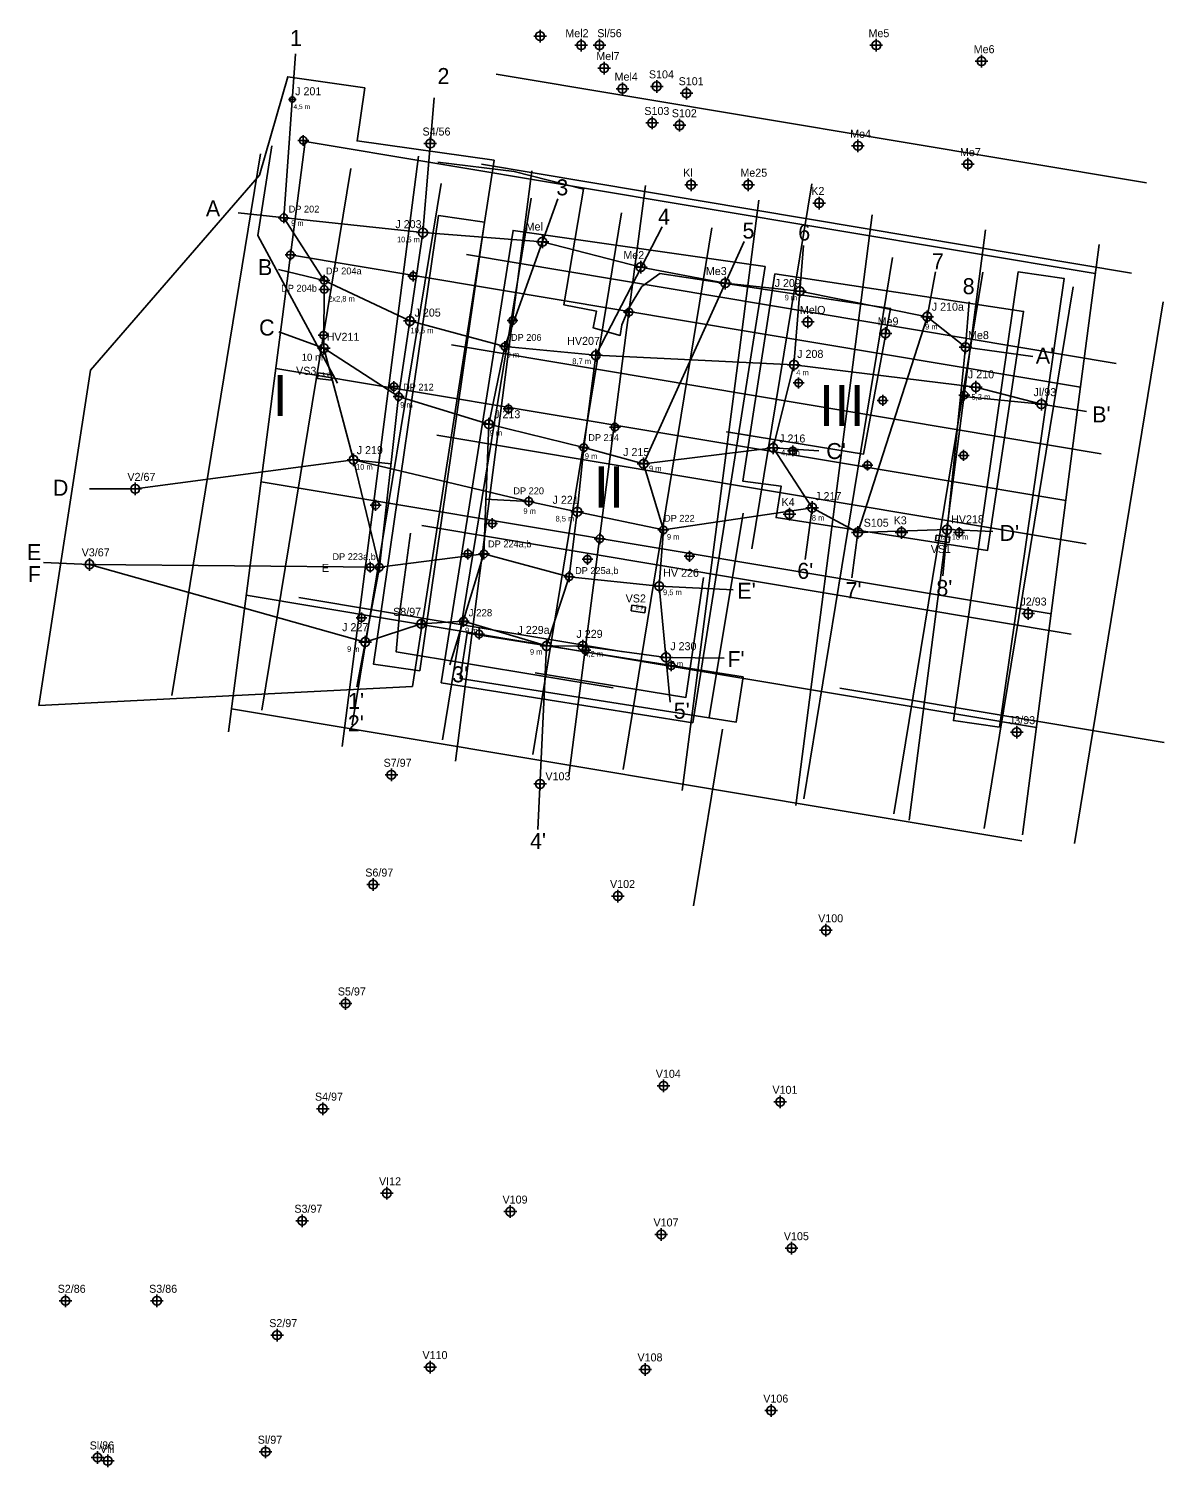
# Model space of a CAD drawing. Extents: x -597749 to -595427, y -1168718 to -1166900.
# Drawn here: x -597567 to -597070, y -1168718 to -1168089 of the extents above; entities that cross this region are included whole.
import ezdxf

# ---------------------------------------------------------------- set-up
doc = ezdxf.new("R2010")
doc.units = 0
for name, color, linetype in [('13_archivní průzkum', 7, 'Continuous'), ('40 m vrty', 7, 'Continuous'), ('50 m', 7, 'Continuous'), ('50 m vrty', 7, 'Continuous'), ('groma_bod', 7, 'Continuous'), ('groma_cislo', 7, 'Continuous'), ('IG řezy', 7, 'Continuous'), ('Nova Šrafy Hranice', 7, 'Continuous'), ('oblasti', 7, 'Continuous'), ('pomocna', 7, 'Continuous'), ('Silový kabel', 7, 'Continuous'), ('vsakovací jímky', 7, 'Continuous'), ('zaměření 24_4_2017', 7, 'Continuous')]:
    doc.layers.add(name, color=color, linetype=linetype)

# ---------------------------------------------------------------- blocks, each defined once
blk = doc.blocks.new('IG vrt OK')
for p, q in [((0, 0.198), (0, -0.198)), ((-0.198, 0), (0.198, 0))]:
    blk.add_line(p, q)
blk.add_circle((0, 0), 0.138)

msp = doc.modelspace()

# ---------------------------------------------------------------- linework, layer by layer
for p, q in [((-597362.16, -1168108.59), (-597077.9, -1168156.23)), ((-597465.24, -1168143.45), (-597504.06, -1168380.28)), ((-597425.77, -1168149.92), (-597464.59, -1168386.75)), ((-597368.66, -1168148.05), (-597084.48, -1168195.68)), ((-597386.29, -1168156.4), (-597425.12, -1168393.22)), ((-597224.18, -1168156.54), (-597250.35, -1168316.14)), ((-597346.82, -1168162.87), (-597385.65, -1168399.69)), ((-597307.35, -1168169.34), (-597346.17, -1168406.17)), ((-597267.87, -1168175.81), (-597306.7, -1168412.64)), ((-597375.16, -1168187.52), (-597091.07, -1168235.14)), ((-597188.93, -1168188.75), (-597227.75, -1168425.58)), ((-597149.46, -1168195.22), (-597188.28, -1168432.05)), ((-597109.98, -1168201.69), (-597148.81, -1168438.52)), ((-597070.51, -1168208.17), (-597109.33, -1168444.99)), ((-597381.66, -1168226.99), (-597097.65, -1168274.59)), ((-597388.16, -1168266.46), (-597104.24, -1168314.05)), ((-597394.66, -1168305.93), (-597110.82, -1168353.5)), ((-597448.45, -1168337.47), (-597306.58, -1168361.25)), ((-597211.99, -1168377.1), (-597070.11, -1168400.88)), ((-597263.29, -1168395.08), (-597275.95, -1168472.31))]:
    msp.add_line(p, q)
at = {"layer": '50 m'}
for p, q in [((-597445.71, -1168138.05), (-597100.27, -1168195.84)), ((-597452.14, -1168187.67), (-597106.7, -1168245.46)), ((-597458.57, -1168237.29), (-597113.13, -1168295.08)), ((-597465, -1168286.91), (-597119.56, -1168344.69)), ((-597471.43, -1168336.52), (-597125.99, -1168394.31)), ((-597477.86, -1168386.14), (-597132.42, -1168443.93))]:
    msp.add_line(p, q, dxfattribs=at)
for points in [[(-597445.72, -1168138.09), (-597454.2, -1168203.57), (-597479.17, -1168396.23)], [(-597396.13, -1168144.52), (-597404.61, -1168209.99), (-597429.58, -1168402.65)], [(-597346.54, -1168150.94), (-597355.03, -1168216.42), (-597380, -1168409.08)], [(-597296.96, -1168157.37), (-597305.44, -1168222.84), (-597330.41, -1168415.51)], [(-597247.37, -1168163.79), (-597255.86, -1168229.27), (-597280.83, -1168421.93)], [(-597197.79, -1168170.22), (-597206.27, -1168235.7), (-597231.24, -1168428.36)], [(-597148.2, -1168176.65), (-597156.69, -1168242.12), (-597181.65, -1168434.78)], [(-597098.62, -1168183.07), (-597107.1, -1168248.55), (-597132.07, -1168441.21)]]:
    msp.add_lwpolyline(points, dxfattribs=at)
at = {"layer": 'groma_bod'}
for p, q in [((-597438.23, -1168241.13), (-597438.23, -1168241.13)), ((-597438.12, -1168240.33), (-597438.12, -1168240.33)), ((-597436.25, -1168241.41), (-597436.25, -1168241.41)), ((-597436.14, -1168240.62), (-597436.14, -1168240.62)), ((-597168.02, -1168312.03), (-597168.02, -1168312.03)), ((-597167.9, -1168311.24), (-597167.9, -1168311.24)), ((-597166.04, -1168312.32), (-597166.04, -1168312.32)), ((-597165.92, -1168311.53), (-597165.92, -1168311.53)), ((-597300.95, -1168341.98), (-597300.95, -1168341.98)), ((-597298.97, -1168342.27), (-597298.97, -1168342.27)), ((-597301.07, -1168342.77), (-597301.07, -1168342.77)), ((-597299.09, -1168343.06), (-597299.09, -1168343.06))]:
    msp.add_line(p, q, dxfattribs=at)
at = {"layer": 'IG řezy'}
for points in [[(-597449.87, -1168099.8), (-597455.09, -1168171.45), (-597437.35, -1168198.8), (-597437.51, -1168228.48), (-597424.58, -1168277.25), (-597413.22, -1168324.22), (-597423.17, -1168376.6)], [(-597413.22, -1168324.22), (-597404.85, -1168249.6), (-597399.91, -1168216.57), (-597394.21, -1168177.95), (-597389.36, -1168119.07)], [(-597335.28, -1168163.16), (-597358.34, -1168227.78), (-597365.44, -1168261.65), (-597367.53, -1168318.28), (-597382.39, -1168366.95)], [(-597474.97, -1168169.32), (-597394.21, -1168177.95), (-597342, -1168182), (-597299, -1168193), (-597262, -1168200), (-597229.45, -1168203.52), (-597173.72, -1168214.7), (-597157, -1168228), (-597127.53, -1168232.16)], [(-597289.61, -1168175.34), (-597318.62, -1168231.59), (-597323.89, -1168271.9), (-597326.71, -1168299.99), (-597330.28, -1168328.41), (-597340.19, -1168358.66), (-597343.95, -1168438.98)], [(-597253.76, -1168181.78), (-597297.73, -1168279.03), (-597289.09, -1168307.9), (-597290.88, -1168332.38), (-597286.05, -1168383.2)], [(-597227.87, -1168183.59), (-597229.45, -1168203.52), (-597231.99, -1168235.71), (-597241.06, -1168272.03), (-597224.01, -1168298.2), (-597227.12, -1168320.8)], [(-597457.34, -1168194.1), (-597437.35, -1168198.8), (-597399.91, -1168216.57), (-597358.34, -1168227.78), (-597318.62, -1168231.59), (-597231.99, -1168235.71), (-597152.46, -1168245.5), (-597123.82, -1168252.94), (-597104.07, -1168256.09)], [(-597170.13, -1168195.02), (-597173.72, -1168214.86), (-597204, -1168309), (-597206.73, -1168328.81)], [(-597155.4, -1168208.24), (-597157, -1168228), (-597165.06, -1168307.79), (-597166.92, -1168328.03)], [(-597457.24, -1168221.35), (-597437.51, -1168228.48), (-597404.85, -1168249.6), (-597365.44, -1168261.65), (-597323.89, -1168271.9), (-597297.73, -1168279.03), (-597241.06, -1168272.03), (-597221.1, -1168273.32)], [(-597540, -1168290), (-597520, -1168290), (-597424.58, -1168277.25), (-597347.94, -1168295.43), (-597326.71, -1168299.99), (-597289.09, -1168307.9), (-597224.01, -1168298.2), (-597204, -1168309), (-597165.06, -1168307.79), (-597145.01, -1168308.67)], [(-597560.08, -1168322.21), (-597540, -1168323), (-597419.44, -1168356.96), (-597395, -1168349), (-597376.45, -1168347.85), (-597340.19, -1168358.66), (-597324.35, -1168358.7), (-597287.91, -1168363.64), (-597262.45, -1168363.98)], [(-597540, -1168323), (-597413.22, -1168324.22), (-597367.53, -1168318.42), (-597330.28, -1168328.41), (-597291.04, -1168332.46), (-597258.62, -1168334.11)]]:
    msp.add_lwpolyline(points, dxfattribs=at)
at = {"layer": 'Nova Šrafy Hranice'}
for p, q in [((-597254.18, -1168300.64), (-597269.01, -1168389.9)), ((-597269.01, -1168389.9), (-597269.04, -1168390.08))]:
    msp.add_line(p, q, dxfattribs=at)
at = {"layer": 'oblasti'}
for points in [[(-597363, -1168146.29), (-597398.78, -1168376.37), (-597562.09, -1168384.66), (-597539.58, -1168238.06), (-597465.72, -1168152.82), (-597453.34, -1168109.77), (-597419.62, -1168114.64), (-597422.97, -1168137.87)], [(-597244.57, -1168192.7), (-597276.27, -1168392.21), (-597386.22, -1168374.74), (-597354.79, -1168176.94)], [(-597240.32, -1168196), (-597131.62, -1168212.37), (-597147.37, -1168316.9), (-597239.79, -1168302.53), (-597237.65, -1168288.77), (-597254.4, -1168286.54)]]:
    msp.add_lwpolyline(points, close=True, dxfattribs=at)
at = {"layer": 'pomocna'}
for p, q in [((-597158.69, -1168244.88), (-597152.46, -1168245.5)), ((-597159.14, -1168249.41), (-597123.82, -1168252.94)), ((-597408.16, -1168279.09), (-597424.58, -1168277.25)), ((-597367.03, -1168294.51), (-597347.94, -1168295.43))]:
    msp.add_line(p, q, dxfattribs=at)
at = {"layer": 'Silový kabel'}
for points in [[(-597460.25, -1168140.03), (-597466.36, -1168179.17), (-597431.54, -1168243.72)], [(-597251.4, -1168266.68), (-597261.43, -1168265.05), (-597201.57, -1168274.75), (-597189.73, -1168211.07), (-597290.61, -1168195.88), (-597298.51, -1168201.51), (-597304.04, -1168210.66), (-597307.21, -1168218.22), (-597307.92, -1168222.88), (-597319.79, -1168219.55), (-597318.36, -1168212.28), (-597332.57, -1168209.53), (-597323.96, -1168158.92), (-597354.29, -1168151.22), (-597387.68, -1168147.18)], [(-597399.62, -1168309.28), (-597404.5, -1168344.65), (-597405.97, -1168361.2), (-597311.02, -1168376.98)], [(-597271.53, -1168328.77), (-597279.2, -1168381.17), (-597345.13, -1168370.36)]]:
    msp.add_lwpolyline(points, dxfattribs=at)
for points in [[(-597395.64, -1168369.58), (-597367.31, -1168173.42), (-597387.47, -1168170.51), (-597415.8, -1168366.67)], [(-597142.16, -1168394.22), (-597113.83, -1168198.06), (-597133.99, -1168195.15), (-597162.31, -1168391.31)], [(-597254.19, -1168372.16), (-597374.81, -1168353.06), (-597377.95, -1168372.89), (-597257.33, -1168391.99)]]:
    msp.add_lwpolyline(points, close=True, dxfattribs=at)
at = {"layer": 'vsakovací jímky'}
for points in [[(-597439.99, -1168239.25), (-597440.32, -1168241.65), (-597434.38, -1168242.49), (-597434.05, -1168240.12)], [(-597169.76, -1168310.16), (-597170.12, -1168312.53), (-597164.18, -1168313.4), (-597163.82, -1168311.03)], [(-597302.81, -1168340.9), (-597303.17, -1168343.27), (-597297.23, -1168344.14), (-597296.87, -1168341.77)]]:
    msp.add_lwpolyline(points, close=True, dxfattribs=at)

# ---------------------------------------------------------------- block references
at = {"layer": '13_archivní průzkum', "xscale": 13.9855072, "yscale": 13.9855072}
for p in [(-597343, -1168092), (-597325, -1168096), (-597317, -1168096), (-597196, -1168096), (-597315, -1168106), (-597150, -1168103), (-597307, -1168115), (-597292, -1168114), (-597279, -1168117), (-597294, -1168130), (-597282, -1168131), (-597391, -1168139), (-597204, -1168140), (-597156, -1168148), (-597277, -1168157), (-597252, -1168157), (-597221, -1168165), (-597342, -1168182), (-597299, -1168193), (-597262, -1168200), (-597226, -1168217), (-597192, -1168222), (-597157, -1168228), (-597123.82, -1168252.94), (-597520, -1168290), (-597234, -1168301), (-597204, -1168309), (-597185, -1168309), (-597540, -1168323), (-597129.57, -1168344.52), (-597395, -1168349), (-597134.6, -1168396.37), (-597408, -1168415), (-597343, -1168419), (-597416, -1168463), (-597309, -1168468), (-597218, -1168483), (-597428, -1168515), (-597289, -1168551), (-597238, -1168558), (-597438, -1168561), (-597410, -1168598), (-597356, -1168606), (-597447, -1168610), (-597290, -1168616), (-597233, -1168622), (-597550.5, -1168645), (-597510.5, -1168645), (-597458, -1168660), (-597391, -1168674), (-597297, -1168675), (-597242, -1168693), (-597536.5, -1168713.5), (-597532, -1168715), (-597463, -1168711)]:
    msp.add_blockref('IG vrt OK', p, dxfattribs=at)
at = {"layer": '40 m vrty'}
for p, xscale, yscale in [((-597451.32, -1168119.74), 8.399999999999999, 8.399999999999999), ((-597455.09, -1168171.45), 12, 12), ((-597394.21, -1168177.95), 14, 14), ((-597437.35, -1168198.8), 12, 12), ((-597437.35, -1168202.8), 12, 12), ((-597399.91, -1168216.57), 14, 14), ((-597437.51, -1168228.48), 14, 14), ((-597358.34, -1168227.78), 12, 12), ((-597318.62, -1168231.59), 14, 14), ((-597231.99, -1168235.71), 14, 14), ((-597404.85, -1168249.6), 12, 12), ((-597365.44, -1168261.65), 14, 14), ((-597323.89, -1168271.9), 12, 12), ((-597424.58, -1168277.25), 14, 14), ((-597297.73, -1168279.03), 14, 14), ((-597347.94, -1168295.43), 12, 12), ((-597326.71, -1168299.99), 14, 14), ((-597289.09, -1168307.9), 12, 12), ((-597165.06, -1168307.79), 14, 14), ((-597374.53, -1168318.42), 12, 12), ((-597367.53, -1168318.42), 12, 12), ((-597417.22, -1168324.22), 12, 12), ((-597413.22, -1168324.22), 12, 12), ((-597322.27, -1168320.75), 12, 12), ((-597330.28, -1168328.41), 12, 12), ((-597290.9, -1168332.52), 14, 14), ((-597419.44, -1168356.96), 14, 14), ((-597287.91, -1168363.64), 14, 14)]:
    msp.add_blockref('IG vrt OK', p, dxfattribs=dict(at, xscale=xscale, yscale=yscale))
at = {"layer": '50 m vrty', "xscale": 12, "yscale": 12}
for p in [(-597446.54, -1168137.65), (-597452.14, -1168187.67), (-597398.49, -1168196.92), (-597304.11, -1168212.71), (-597355.03, -1168216.42), (-597437.67, -1168222.79), (-597229.96, -1168243.65), (-597406.91, -1168245.25), (-597157.53, -1168248.96), (-597356.82, -1168255.01), (-597193.21, -1168251.27), (-597310.28, -1168262.99), (-597232.5, -1168273.35), (-597157.8, -1168275.33), (-597199.82, -1168279.64), (-597414.89, -1168297.14), (-597363.92, -1168305.12), (-597316.93, -1168311.77), (-597159.8, -1168309.03), (-597277.65, -1168319.47), (-597421.1, -1168346.36), (-597369.68, -1168353.45), (-597323.14, -1168360.55), (-597285.63, -1168367.36)]:
    msp.add_blockref('IG vrt OK', p, dxfattribs=at)
at = {"layer": 'zaměření 24_4_2017'}
for p, xscale, yscale in [((-597229.45, -1168203.52), 14, 14), ((-597173.72, -1168214.7), 14, 14), ((-597152.46, -1168245.5), 14, 14), ((-597241.06, -1168272.03), 14, 14), ((-597224.01, -1168298.2), 14, 14), ((-597376.45, -1168347.85), 12.6, 12.6), ((-597340.19, -1168358.66), 14, 14), ((-597324.35, -1168358.7), 14, 14)]:
    msp.add_blockref('IG vrt OK', p, dxfattribs=dict(at, xscale=xscale, yscale=yscale))

# ---------------------------------------------------------------- texts
at = {"layer": '13_archivní průzkum'}
for s, p in [('Mel2', (-597331.95, -1168092.49)), ('Sl/56', (-597317.98, -1168092.49)), ('Me5', (-597199.41, -1168092.49)), ('Me6', (-597153.41, -1168099.49)), ('Mel7', (-597318.41, -1168102.49)), ('Mel4', (-597310.41, -1168111.49)), ('S104', (-597295.41, -1168110.49)), ('S101', (-597282.41, -1168113.49)), ('S103', (-597297.41, -1168126.49)), ('S102', (-597285.41, -1168127.49)), ('S4/56', (-597394.41, -1168135.49)), ('Me4', (-597207.41, -1168136.49)), ('Me7', (-597159.41, -1168144.49)), ('Kl', (-597280.41, -1168153.49)), ('Me25', (-597255.41, -1168153.49)), ('K2', (-597224.41, -1168161.49)), ('Mel', (-597349.3, -1168177.03)), ('Me2', (-597306.58, -1168189.49)), ('Me3', (-597270.51, -1168196.49)), ('MelO', (-597229.41, -1168213.49)), ('Me9', (-597195.41, -1168218.49)), ('Me8', (-597155.89, -1168224.49)), ('Jl/93', (-597127.23, -1168249.43)), ('V2/67', (-597523.41, -1168286.49)), ('K4', (-597237.41, -1168297.49)), ('S105', (-597201.5, -1168306.53)), ('K3', (-597188.41, -1168305.49)), ('V3/67', (-597543.41, -1168319.49)), ('S8/97', (-597407.24, -1168345.49)), ('J2/93', (-597132.98, -1168341.01)), ('J3/93', (-597138.01, -1168392.86)), ('S7/97', (-597411.41, -1168411.49)), ('V103', (-597340.66, -1168417.4)), ('S6/97', (-597419.41, -1168459.49)), ('V102', (-597312.41, -1168464.49)), ('V100', (-597221.41, -1168479.49)), ('S5/97', (-597431.41, -1168511.49)), ('V104', (-597292.41, -1168547.49)), ('S4/97', (-597441.41, -1168557.49)), ('V101', (-597241.41, -1168554.49)), ('VI12', (-597413.41, -1168594.49)), ('V109', (-597359.41, -1168602.49)), ('S3/97', (-597450.41, -1168606.49)), ('V107', (-597293.41, -1168612.49)), ('V105', (-597236.41, -1168618.49)), ('S2/86', (-597553.91, -1168641.49)), ('S3/86', (-597513.91, -1168641.49)), ('S2/97', (-597461.41, -1168656.49)), ('V110', (-597394.41, -1168670.49)), ('V108', (-597300.41, -1168671.49)), ('V106', (-597245.41, -1168689.49)), ('Sl/86', (-597539.91, -1168709.99)), ('Sl/97', (-597466.41, -1168707.49)), ('Vlil', (-597535.41, -1168711.49))]:
    msp.add_text(s, height=3.5, dxfattribs=at).set_placement(p)
at = {"layer": '40 m vrty'}
for s, height, p in [('J 201', 3.5, (-597450.08, -1168117.88)), ('4,5 m', 2.1, (-597450.82, -1168123.9)), ('DP 202', 3, (-597452.9, -1168169.14)), ('9 m', 2.45, (-597451.84, -1168175.01)), ('J 203', 3.5, (-597406.27, -1168175.99)), ('10,5 m', 2.45, (-597405.57, -1168182.18)), ('DP 204a', 3, (-597436.63, -1168196.2)), ('DP 204b', 3, (-597456.18, -1168203.75)), ('2x2,8 m', 2.45, (-597435.66, -1168208.07)), ('J 205', 3.5, (-597397.88, -1168214.64)), ('HV211', 3.5, (-597436.31, -1168225.25)), ('10,5 m', 2.45, (-597399.64, -1168221.93)), ('DP 206', 3, (-597355.73, -1168225.28)), ('HV207', 3.5, (-597331.14, -1168227.01)), ('J 208', 3.5, (-597230.58, -1168232.71)), ('10 m', 3.15, (-597447.24, -1168233.99)), ('9 m', 2.45, (-597357.58, -1168232.54)), ('8,7 m', 2.45, (-597328.91, -1168235.42)), ('4 m', 2.45, (-597230.99, -1168240.37)), ('J 210', 3.5, (-597155.95, -1168241.66)), ('DP 212', 3, (-597402.88, -1168247)), ('9 m', 2.45, (-597404.16, -1168254.48)), ('5,2 m', 2.45, (-597154.36, -1168250.96)), ('J 213', 3.5, (-597363.09, -1168259.1)), ('9 m', 2.45, (-597365.03, -1168266.71)), ('DP 214', 3, (-597321.91, -1168269.04)), ('J 216', 3.5, (-597238.48, -1168269.7)), ('J 219', 3.5, (-597423.15, -1168274.8)), ('J 215', 3.5, (-597306.68, -1168275.63)), ('4,2 m', 2.45, (-597237.65, -1168275.37)), ('10 m', 2.45, (-597423.47, -1168281.57)), ('9 m', 2.45, (-597323.45, -1168276.89)), ('9 m', 2.45, (-597295.35, -1168282.28)), ('DP 220', 3, (-597354.67, -1168292.34)), ('9 m', 2.45, (-597350.28, -1168300.9)), ('J 221', 3.5, (-597337.53, -1168296.51)), ('8,5 m', 2.45, (-597336.23, -1168304.23)), ('DP 222', 3, (-597288.79, -1168304.36)), ('HV218', 3.5, (-597163.29, -1168305)), ('9 m', 2.45, (-597287.53, -1168312.18)), ('10 m', 2.45, (-597163.04, -1168312.24)), ('DP 224a,b', 3, (-597365.73, -1168315.55)), ('DP 223a,b', 3, (-597433.78, -1168321.12)), ('DP 225a,b', 3, (-597327.68, -1168327.21)), ('HV 226', 3.5, (-597289.18, -1168328.44)), ('9,5 m', 2.45, (-597289.22, -1168336.44)), ('J 227', 3.5, (-597429.53, -1168352.2)), ('J 229', 3.5, (-597327.1, -1168355.12)), ('9 m', 2.45, (-597427.37, -1168361.25)), ('4,2 m', 2.45, (-597323.67, -1168363.31)), ('J 230', 3.5, (-597286.07, -1168360.52)), ('8 m', 2.45, (-597285.91, -1168367.72))]:
    msp.add_text(s, height=height, dxfattribs=at).set_placement(p)
at = {"layer": 'groma_cislo'}
for s, p in [('4', (-597438.23, -1168241.13)), ('1', (-597438.12, -1168240.33)), ('3', (-597436.25, -1168241.41)), ('2', (-597436.14, -1168240.62)), ('12', (-597168.02, -1168312.03)), ('9', (-597167.9, -1168311.24)), ('11', (-597166.04, -1168312.32)), ('10', (-597165.92, -1168311.53)), ('8', (-597301.07, -1168342.77)), ('5', (-597300.95, -1168341.98)), ('7', (-597299.09, -1168343.06)), ('6', (-597298.97, -1168342.27))]:
    msp.add_text(s, height=1.5, dxfattribs=at).set_placement(p)
at = {"layer": 'IG řezy'}
for s, height, p in [('1', 7, (-597452.3, -1168096.33)), ('2', 7, (-597387.85, -1168112.97)), ('3', 7, (-597335.89, -1168161.64)), ('A', 7, (-597489.11, -1168170.83)), ('4', 7, (-597291.42, -1168174.42)), ('5', 7, (-597254.49, -1168180.55)), ('6', 7, (-597230.1, -1168181.36)), ('B', 7, (-597466.31, -1168196.53)), ('7', 7, (-597171.65, -1168193.98)), ('8', 7, (-597158.22, -1168204.86)), ('C', 7, (-597465.85, -1168222.94)), ("A'", 7, (-597126.25, -1168235.21)), ("B'", 7, (-597101.58, -1168260.93)), ("C'", 7, (-597217.85, -1168276.94)), ('D', 7, (-597555.99, -1168292.99)), ("D'", 7, (-597142.11, -1168312.75)), ('E', 7, (-597567.31, -1168321.15)), ('E', 3.5, (-597438.37, -1168326.26)), ("6'", 7, (-597230.53, -1168329.33)), ('F', 7, (-597566.98, -1168330.77)), ("8'", 7, (-597169.73, -1168336.81)), ("E'", 7, (-597256.73, -1168338.05)), ("7'", 7, (-597209.41, -1168337.77)), ("F'", 7, (-597261.09, -1168367.93)), ("3'", 7, (-597381.43, -1168374.57)), ("1'", 7, (-597426.94, -1168386.17)), ("5'", 7, (-597284.55, -1168390.48)), ("2'", 7, (-597427.01, -1168395.95)), ("4'", 7, (-597347.39, -1168447.49))]:
    msp.add_text(s, height=height, dxfattribs=at).set_placement(p)
at = {"layer": 'oblasti'}
for s, p in [('I', (-597459.98, -1168258.12)), ('III', (-597221.12, -1168262.53)), ('II', (-597319.58, -1168298.16))]:
    msp.add_text(s, height=18, dxfattribs=at).set_placement(p)
at = {"layer": 'vsakovací jímky'}
for s, p in [('VS3', (-597449.67, -1168240.1)), ('VS1', (-597172.19, -1168318.03)), ('VS2', (-597305.57, -1168339.65))]:
    msp.add_text(s, height=3.5, dxfattribs=at).set_placement(p)
at = {"layer": 'zaměření 24_4_2017'}
for s, height, p in [('J 209', 3.5, (-597240.44, -1168201.73)), ('9 m', 2.45, (-597236.05, -1168207.58)), ('J 210a', 3.5, (-597171.74, -1168212.09)), ('9 m', 2.45, (-597174.66, -1168220.28)), ('J 217', 3.5, (-597222.71, -1168294.91)), ('8 m', 2.45, (-597224.19, -1168303.89)), ('J 228', 3.15, (-597374.22, -1168345.71)), ('9 m', 2.45, (-597375.8, -1168353.1)), ('J 229a', 3.5, (-597352.87, -1168353.41)), ('9 m', 2.45, (-597347.41, -1168362.48))]:
    msp.add_text(s, height=height, dxfattribs=at).set_placement(p)

doc.saveas('drawing.dxf')
